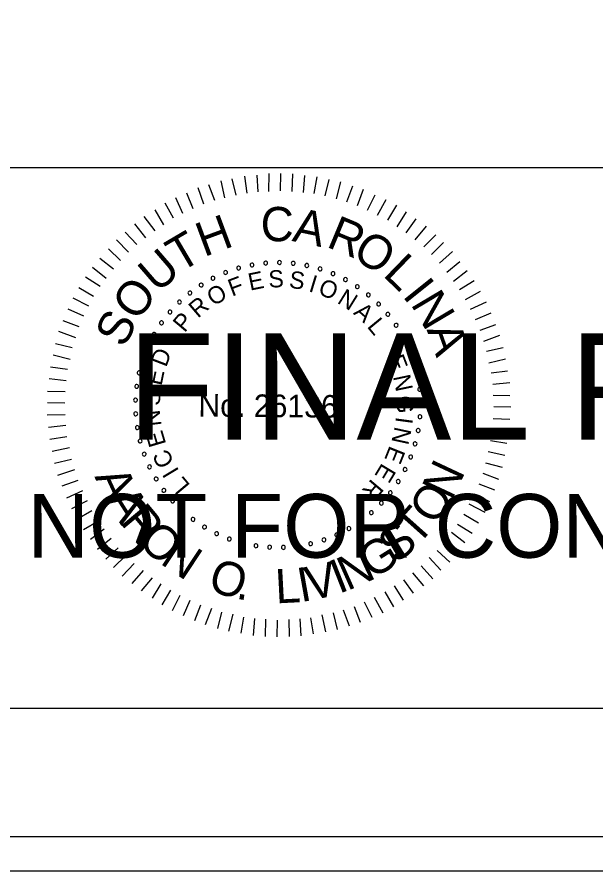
# Model space of a CAD drawing. Extents: x 967 to 1326, y 964 to 2864.
# Drawn here: x 1170.56 to 1189.3, y 1803.72 to 1831.36 of the extents above; entities that cross this region are included whole.
import ezdxf

# ---------------------------------------------------------------- set-up
doc = ezdxf.new("R2010")
doc.units = 0
for name, color, linetype in [('RD_PD_Final_TX', 7, 'Continuous'), ('RD_XS_TX_Elev_PR', 7, 'Continuous'), ('RD_XS_TX_Misc', 7, 'Continuous'), ('RD_XS_TX_ShdSlope', 7, 'Continuous')]:
    doc.layers.add(name, color=color, linetype=linetype)

msp = doc.modelspace()

# ---------------------------------------------------------------- linework, layer by layer
at = {"layer": 'RD_PD_Final_TX'}
for p, q in [((996.114, 1826.486), (1323.886, 1826.486)), ((1323.886, 1808.983), (996.114, 1808.983))]:
    msp.add_line(p, q, dxfattribs=at)
at = {"layer": 'RD_XS_TX_Elev_PR'}
for points in [[(967.409, 1803.72), (1326.285, 1803.72), (1326.285, 2023.72), (967.409, 2023.72)], [(988.525, 1804.84), (1326.285, 1804.84), (1326.285, 2022.6), (988.525, 2022.6)]]:
    msp.add_lwpolyline(points, close=True, dxfattribs=at)
at = {"layer": 'RD_XS_TX_ShdSlope'}
for p, q in [((1178.01, 1825.663), (1177.93, 1826.209)), ((1178.364, 1825.699), (1178.33, 1826.244)), ((1178.717, 1825.719), (1178.722, 1826.295)), ((1179.093, 1825.739), (1179.098, 1826.292)), ((1179.469, 1825.713), (1179.489, 1826.288)), ((1179.829, 1825.687), (1179.872, 1826.231)), ((1180.174, 1825.646), (1180.271, 1826.19)), ((1176.964, 1825.419), (1176.769, 1825.935)), ((1177.287, 1825.508), (1177.169, 1826.054)), ((1177.657, 1825.597), (1177.53, 1826.128)), ((1180.535, 1825.573), (1180.662, 1826.102)), ((1180.902, 1825.478), (1181.045, 1826.022)), ((1181.231, 1825.384), (1181.428, 1825.896)), ((1176.264, 1825.156), (1176.053, 1825.657)), ((1176.61, 1825.306), (1176.423, 1825.83)), ((1181.584, 1825.265), (1181.78, 1825.786)), ((1181.905, 1825.109), (1182.154, 1825.606)), ((1175.624, 1824.846), (1175.352, 1825.332)), ((1175.933, 1825.005), (1175.699, 1825.506)), ((1182.226, 1824.953), (1182.506, 1825.45)), ((1175.308, 1824.634), (1175.036, 1825.12)), ((1182.562, 1824.789), (1182.85, 1825.27)), ((1175.03, 1824.445), (1174.681, 1824.9)), ((1182.86, 1824.572), (1183.163, 1825.053)), ((1183.158, 1824.378), (1183.484, 1824.828)), ((1174.729, 1824.217), (1174.372, 1824.665)), ((1183.447, 1824.145), (1183.811, 1824.587)), ((1174.435, 1823.997), (1174.062, 1824.399)), ((1183.729, 1823.92), (1184.116, 1824.316)), ((1174.172, 1823.753), (1173.776, 1824.148)), ((1183.98, 1823.672), (1184.368, 1824.061)), ((1173.909, 1823.479), (1173.52, 1823.858)), ((1184.232, 1823.394), (1184.657, 1823.767)), ((1173.684, 1823.197), (1173.242, 1823.546)), ((1184.475, 1823.108), (1184.892, 1823.45)), ((1173.451, 1822.9), (1173.009, 1823.256)), ((1184.687, 1822.807), (1185.128, 1823.156)), ((1173.257, 1822.64), (1172.776, 1822.936)), ((1173.039, 1822.312), (1172.559, 1822.6)), ((1184.885, 1822.544), (1185.355, 1822.832)), ((1185.081, 1822.213), (1185.56, 1822.493)), ((1172.883, 1822.006), (1172.379, 1822.256)), ((1185.24, 1821.904), (1185.756, 1822.145)), ((1172.727, 1821.677), (1172.215, 1821.904)), ((1185.399, 1821.573), (1185.907, 1821.791)), ((1172.571, 1821.333), (1172.051, 1821.53)), ((1185.549, 1821.226), (1186.057, 1821.414)), ((1172.461, 1820.974), (1171.91, 1821.178)), ((1185.669, 1820.865), (1186.185, 1821.06)), ((1172.351, 1820.652), (1171.807, 1820.787)), ((1185.759, 1820.541), (1186.297, 1820.667)), ((1172.286, 1820.276), (1171.727, 1820.419)), ((1185.832, 1820.165), (1186.371, 1820.298)), ((1172.191, 1819.955), (1171.647, 1820.029)), ((1185.906, 1819.842), (1186.436, 1819.906)), ((1172.15, 1819.587), (1171.598, 1819.653)), ((1185.964, 1819.473), (1186.51, 1819.53)), ((1172.124, 1819.234), (1171.548, 1819.239)), ((1185.977, 1819.12), (1186.514, 1819.115)), ((1172.105, 1818.866), (1171.545, 1818.871)), ((1185.997, 1818.751), (1186.542, 1818.747)), ((1172.118, 1818.482), (1171.542, 1818.471)), ((1185.971, 1818.368), (1186.508, 1818.348)), ((1172.138, 1818.136), (1171.585, 1818.072)), ((1185.952, 1818.022), (1186.497, 1817.949)), ((1172.173, 1817.768), (1171.627, 1817.688)), ((1185.888, 1817.655), (1186.417, 1817.566)), ((1172.262, 1817.414), (1171.701, 1817.296)), ((1185.808, 1817.302), (1186.345, 1817.175)), ((1172.321, 1817.037), (1171.774, 1816.911)), ((1185.729, 1816.926), (1186.265, 1816.792)), ((1172.425, 1816.707), (1171.871, 1816.519)), ((1185.634, 1816.597), (1186.146, 1816.401)), ((1172.53, 1816.36), (1172.007, 1816.173)), ((1185.508, 1816.253), (1186.013, 1816.057)), ((1172.681, 1816.029), (1172.165, 1815.788)), ((1172.831, 1815.705), (1172.323, 1815.441)), ((1185.352, 1815.924), (1185.857, 1815.675)), ((1185.188, 1815.603), (1185.7, 1815.33)), ((1172.982, 1815.374), (1172.497, 1815.094)), ((1185.024, 1815.274), (1185.498, 1814.987)), ((1173.194, 1815.042), (1172.709, 1814.762)), ((1184.822, 1814.946), (1185.288, 1814.658)), ((1173.384, 1814.78), (1172.936, 1814.453)), ((1184.62, 1814.687), (1185.055, 1814.353)), ((1173.612, 1814.478), (1173.164, 1814.129)), ((1184.403, 1814.389), (1184.814, 1814.033)), ((1173.832, 1814.177), (1173.437, 1813.812)), ((1184.155, 1814.092), (1184.574, 1813.72)), ((1174.091, 1813.945), (1173.689, 1813.541)), ((1183.899, 1813.864), (1184.28, 1813.454)), ((1174.35, 1813.674), (1173.97, 1813.263)), ((1183.644, 1813.597), (1184.024, 1813.18)), ((1174.64, 1813.442), (1174.275, 1813.022)), ((1174.937, 1813.209), (1174.58, 1812.782)), ((1183.358, 1813.37), (1183.715, 1812.944)), ((1175.212, 1813.014), (1174.932, 1812.549)), ((1182.764, 1812.952), (1183.059, 1812.482)), ((1183.065, 1813.141), (1183.384, 1812.709)), ((1175.525, 1812.812), (1175.245, 1812.331)), ((1175.83, 1812.633), (1175.588, 1812.136)), ((1182.463, 1812.755), (1182.743, 1812.269)), ((1176.159, 1812.477), (1175.94, 1811.98)), ((1181.8, 1812.431), (1182.041, 1811.93)), ((1182.124, 1812.581), (1182.396, 1812.08)), ((1176.503, 1812.321), (1176.307, 1811.816)), ((1176.855, 1812.211), (1176.651, 1811.69)), ((1177.177, 1812.1), (1177.05, 1811.572)), ((1180.791, 1812.07), (1180.926, 1811.54)), ((1181.122, 1812.175), (1181.31, 1811.652)), ((1181.476, 1812.28), (1181.664, 1811.771)), ((1177.545, 1812.036), (1177.409, 1811.484)), ((1177.897, 1811.933), (1177.808, 1811.412)), ((1178.25, 1811.892), (1178.207, 1811.34)), ((1178.603, 1811.866), (1178.598, 1811.313)), ((1178.978, 1811.84), (1178.974, 1811.295)), ((1179.355, 1811.86), (1179.365, 1811.307)), ((1179.715, 1811.88), (1179.749, 1811.327)), ((1180.061, 1811.915), (1180.149, 1811.393)), ((1180.423, 1812.012), (1180.541, 1811.458))]:
    msp.add_line(p, q, dxfattribs=at)
for centre, start, end in [((1178.168, 1823.337), 10.6038, 190.6038), ((1178.609, 1823.397), 5.0653, 185.0653), ((1178.609, 1823.397), 185.0653, 5.0653), ((1179.055, 1823.414), 359.5268, 179.5268), ((1179.055, 1823.414), 179.5268, 359.5268), ((1179.5, 1823.388), 353.9884, 173.9884), ((1177.312, 1823.091), 21.6807, 201.6807), ((1177.734, 1823.235), 16.1422, 196.1422), ((1177.734, 1823.235), 196.1422, 16.1422), ((1178.168, 1823.337), 190.6038, 10.6038), ((1179.5, 1823.388), 173.9884, 353.9884), ((1179.94, 1823.319), 168.4499, 348.4499), ((1179.94, 1823.319), 348.4499, 168.4499), ((1180.372, 1823.208), 162.9114, 342.9114), ((1180.372, 1823.208), 342.9114, 162.9114), ((1180.79, 1823.056), 337.373, 157.373), ((1176.906, 1822.908), 27.2191, 207.2191), ((1176.906, 1822.908), 207.2191, 27.2191), ((1177.312, 1823.091), 201.6807, 21.6807), ((1180.79, 1823.056), 157.373, 337.373), ((1181.193, 1822.864), 151.8345, 331.8345), ((1181.193, 1822.864), 331.8345, 151.8345), ((1176.52, 1822.686), 32.7576, 212.7576), ((1176.52, 1822.686), 212.7576, 32.7576), ((1181.574, 1822.634), 146.2961, 326.2961), ((1181.574, 1822.634), 326.2961, 146.2961), ((1176.156, 1822.428), 38.2961, 218.2961), ((1176.156, 1822.428), 218.2961, 38.2961), ((1181.932, 1822.368), 140.7576, 320.7576), ((1181.932, 1822.368), 320.7576, 140.7576), ((1175.82, 1822.135), 43.8345, 223.8345), ((1175.82, 1822.135), 223.8345, 43.8345), ((1182.263, 1822.069), 135.2191, 315.2191), ((1182.263, 1822.069), 315.2191, 135.2191), ((1175.513, 1821.812), 49.373, 229.373), ((1175.513, 1821.812), 229.373, 49.373), ((1182.563, 1821.74), 129.6807, 309.6807), ((1182.563, 1821.74), 309.6807, 129.6807), ((1175.239, 1821.461), 54.9114, 234.9114), ((1175.239, 1821.461), 234.9114, 54.9114), ((1182.83, 1821.383), 124.1422, 304.1422), ((1182.83, 1821.383), 304.1422, 124.1422), ((1175, 1821.085), 60.4499, 240.4499), ((1175, 1821.085), 240.4499, 60.4499), ((1183.061, 1821.002), 118.6038, 298.6038), ((1183.061, 1821.002), 298.6038, 118.6038), ((1174.798, 1820.687), 65.9884, 245.9884), ((1174.798, 1820.687), 245.9884, 65.9884), ((1183.255, 1820.601), 113.0653, 293.0653), ((1183.255, 1820.601), 293.0653, 113.0653), ((1174.636, 1820.272), 71.5268, 251.5268), ((1174.636, 1820.272), 251.5268, 71.5268), ((1183.408, 1820.182), 107.5268, 287.5268), ((1183.408, 1820.182), 287.5268, 107.5268), ((1174.514, 1819.843), 77.0653, 257.0653), ((1174.514, 1819.843), 257.0653, 77.0653), ((1183.521, 1819.751), 101.9884, 281.9884), ((1183.521, 1819.751), 281.9884, 101.9884), ((1174.435, 1819.405), 82.6038, 262.6038), ((1174.435, 1819.405), 262.6038, 82.6038), ((1183.592, 1819.311), 96.4499, 276.4499), ((1183.592, 1819.311), 276.4499, 96.4499), ((1174.398, 1818.961), 88.1422, 268.1422), ((1174.398, 1818.961), 268.1422, 88.1422), ((1183.619, 1818.866), 90.9114, 270.9114), ((1183.619, 1818.866), 270.9114, 90.9114), ((1174.404, 1818.515), 93.6807, 273.6807), ((1174.404, 1818.515), 273.6807, 93.6807), ((1183.604, 1818.421), 85.373, 265.373), ((1183.604, 1818.421), 265.373, 85.373), ((1174.453, 1818.072), 99.2191, 279.2191), ((1174.453, 1818.072), 279.2191, 99.2191), ((1183.546, 1817.979), 79.8345, 259.8345), ((1183.546, 1817.979), 259.8345, 79.8345), ((1174.545, 1817.636), 104.7576, 284.7576), ((1174.545, 1817.636), 284.7576, 104.7576), ((1183.445, 1817.545), 74.2961, 254.2961), ((1183.445, 1817.545), 254.2961, 74.2961), ((1174.678, 1817.211), 110.2961, 290.2961), ((1174.678, 1817.211), 290.2961, 110.2961), ((1183.303, 1817.122), 68.7576, 248.7576), ((1183.303, 1817.122), 248.7576, 68.7576), ((1174.852, 1816.8), 115.8345, 295.8345), ((1174.852, 1816.8), 295.8345, 115.8345), ((1183.121, 1816.716), 63.2191, 243.2191), ((1183.121, 1816.716), 243.2191, 63.2191), ((1175.065, 1816.409), 121.373, 301.373), ((1175.065, 1816.409), 301.373, 121.373), ((1182.9, 1816.328), 57.6807, 237.6807), ((1182.9, 1816.328), 237.6807, 57.6807), ((1175.314, 1816.039), 126.9114, 306.9114), ((1175.314, 1816.039), 306.9114, 126.9114), ((1182.643, 1815.964), 52.1422, 232.1422), ((1182.643, 1815.964), 232.1422, 52.1422), ((1175.598, 1815.696), 132.4499, 312.4499), ((1175.598, 1815.696), 312.4499, 132.4499), ((1182.353, 1815.627), 46.6038, 226.6038), ((1182.353, 1815.627), 226.6038, 46.6038), ((1175.914, 1815.381), 137.9884, 317.9884), ((1175.914, 1815.381), 317.9884, 137.9884), ((1182.03, 1815.319), 41.0653, 221.0653), ((1176.258, 1815.099), 143.5268, 323.5268), ((1176.258, 1815.099), 323.5268, 143.5268), ((1181.68, 1815.043), 35.5268, 215.5268), ((1182.03, 1815.319), 221.0653, 41.0653), ((1176.629, 1814.851), 149.0653, 329.0653), ((1176.629, 1814.851), 329.0653, 149.0653), ((1181.305, 1814.803), 29.9884, 209.9884), ((1181.305, 1814.803), 209.9884, 29.9884), ((1181.68, 1815.043), 215.5268, 35.5268), ((1177.021, 1814.639), 154.6038, 334.6038), ((1177.021, 1814.639), 334.6038, 154.6038), ((1180.908, 1814.6), 24.4499, 204.4499), ((1180.908, 1814.6), 204.4499, 24.4499), ((1177.432, 1814.467), 160.1422, 340.1422), ((1177.432, 1814.467), 340.1422, 160.1422), ((1177.858, 1814.335), 165.6807, 345.6807), ((1177.858, 1814.335), 345.6807, 165.6807), ((1178.294, 1814.245), 351.2191, 171.2191), ((1179.627, 1814.232), 7.8345, 187.8345), ((1180.065, 1814.313), 13.373, 193.373), ((1180.065, 1814.313), 193.373, 13.373), ((1180.494, 1814.436), 18.9114, 198.9114), ((1180.494, 1814.436), 198.9114, 18.9114), ((1178.294, 1814.245), 171.2191, 351.2191), ((1178.737, 1814.198), 356.7576, 176.7576), ((1178.737, 1814.198), 176.7576, 356.7576), ((1179.183, 1814.193), 2.2961, 182.2961), ((1179.183, 1814.193), 182.2961, 2.2961), ((1179.627, 1814.232), 187.8345, 7.8345)]:
    msp.add_arc(centre, 0.0627, start, end, dxfattribs=at)

# ---------------------------------------------------------------- texts
at = {"layer": 'RD_XS_TX_Misc'}
for s, height, p in [('FINAL PLANS', 3.4375, (1174.145, 1817.685)), ('NOT FOR CONSTRUCTION', 2.0625, (1170.901, 1813.86))]:
    msp.add_text(s, height=height, dxfattribs=at).set_placement(p)
at = {"layer": 'RD_XS_TX_ShdSlope'}
for s, height, rotation, p in [('C', 1.11, 359.5482, (1178.442, 1824.108)), ('A', 1.11, 348.1981, (1179.439, 1824.115)), ('H', 1.11, 20.3637, (1176.614, 1823.587)), ('R', 1.11, 337.4344, (1180.541, 1823.937)), ('T', 1.11, 30.4992, (1175.828, 1823.072)), ('O', 1.108, 326.5869, (1181.366, 1823.609)), ('U', 1.11, 40.8022, (1175.102, 1822.403)), ('L', 1.11, 315.9488, (1182.373, 1823.003)), ('E', 0.557, 11.4103, (1178.103, 1822.503)), ('S', 0.557, 2.208, (1178.709, 1822.601)), ('S', 0.557, 352.6608, (1179.346, 1822.599)), ('O', 1.11, 52.0267, (1174.435, 1821.474)), ('F', 0.557, 20.6127, (1177.52, 1822.309)), ('I', 0.557, 343.1136, (1179.975, 1822.491)), ('O', 0.557, 338.4392, (1180.274, 1822.401)), ('I', 1.11, 308.6613, (1183.011, 1822.338)), ('O', 0.557, 30.8477, (1176.917, 1821.987)), ('N', 0.557, 328.2042, (1180.896, 1822.12)), ('N', 1.11, 300.7037, (1183.285, 1822.075)), ('R', 0.557, 40.3949, (1176.415, 1821.594)), ('A', 0.557, 318.657, (1181.424, 1821.762)), ('S', 1.108, 63.2511, (1174.029, 1820.619)), ('P', 0.557, 49.9421, (1175.985, 1821.124)), ('L', 0.557, 309.4546, (1181.869, 1821.339)), ('A', 1.11, 289.4792, (1183.814, 1821.243)), ('D', 0.557, 69.0364, (1175.386, 1820.003)), ('E', 0.557, 291.049, (1182.53, 1820.307)), ('E', 0.557, 78.2388, (1175.238, 1819.407)), ('N', 0.557, 281.8466, (1182.728, 1819.726)), ('S', 0.557, 87.786, (1175.187, 1818.772)), ('No. 26136', 0.7311, 359.5268, (1176.429, 1818.43)), ('G', 0.557, 272.2995, (1182.833, 1819.097)), ('N', 0.557, 97.3332, (1175.242, 1818.137)), ('I', 0.557, 262.4084, (1182.83, 1818.437)), ('E', 0.557, 106.5355, (1175.394, 1817.541)), ('N', 0.557, 257.7339, (1182.789, 1818.127)), ('C', 0.557, 116.4266, (1175.661, 1816.938)), ('E', 0.557, 248.1867, (1182.628, 1817.511)), ('I', 0.557, 121.1011, (1175.823, 1816.67)), ('E', 0.557, 238.9844, (1182.378, 1816.949)), ('N', 1.105, 64.8922, (1184.632, 1815.684)), ('A', 1.105, 294.7297, (1173.062, 1816.486)), ('L', 0.557, 129.9595, (1176.187, 1816.204)), ('R', 0.557, 229.782, (1182.041, 1816.435)), ('O', 1.105, 56.2059, (1184.102, 1814.874)), ('A', 1.105, 302.2892, (1173.414, 1815.72)), ('R', 1.105, 309.8487, (1173.865, 1815.007)), ('T', 1.105, 48.2685, (1183.515, 1814.211)), ('O', 1.105, 317.7861, (1174.434, 1814.33)), ('S', 1.105, 40.3311, (1182.842, 1813.636)), ('N', 1.105, 326.4725, (1175.158, 1813.686)), ('G', 1.105, 32.0198, (1182.059, 1813.14)), ('N', 1.105, 24.0824, (1181.252, 1812.776)), ('O', 1.105, 342.3472, (1176.697, 1812.82)), ('V', 1.105, 12.7741, (1180.033, 1812.457)), ('I', 1.105, 21.4605, (1180.976, 1812.681)), ('L', 1.105, 2.9677, (1178.943, 1812.379)), ('I', 1.105, 10.1523, (1179.743, 1812.418)), ('.', 1.105, 351.0336, (1177.623, 1812.536))]:
    msp.add_text(s, height=height, rotation=rotation, dxfattribs=at).set_placement(p)

doc.saveas('drawing.dxf')
